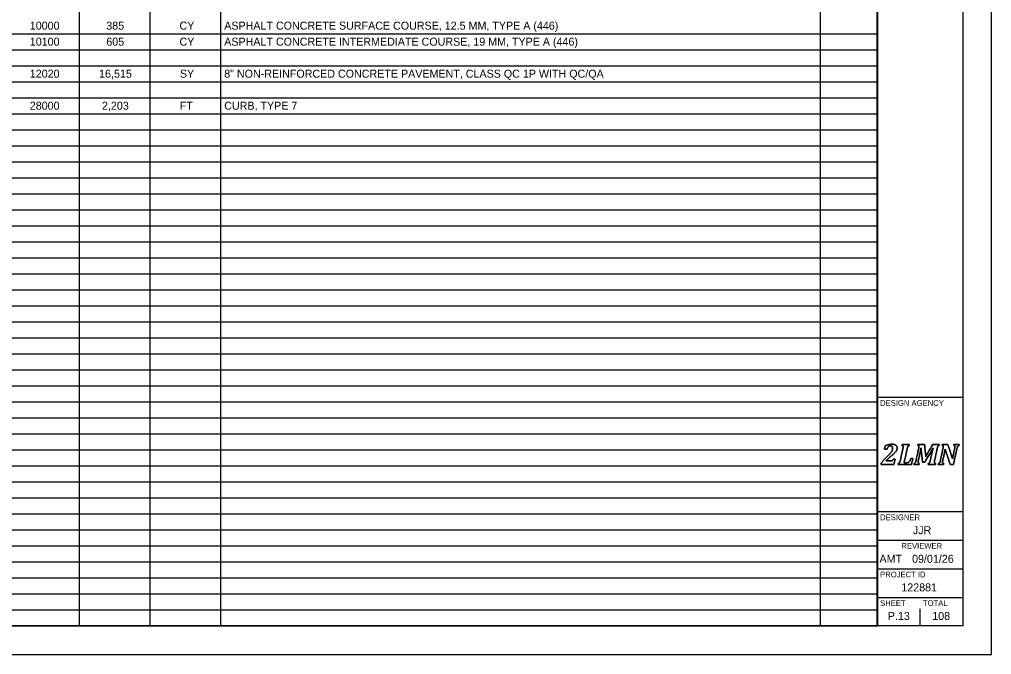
# Model space of a CAD drawing. Extents: x 0 to 34, y 0 to 22.
# Drawn here: x 16.99 to 34, y 0 to 11.11 of the extents above; entities that cross this region are included whole.
import ezdxf

# ---------------------------------------------------------------- set-up
doc = ezdxf.new("R2010")
doc.units = 0
for name, color, linetype in [('SH_Border', 7, 'Continuous'), ('SH_Cut_Line', 7, 'Continuous'), ('SH_Data', 7, 'Continuous'), ('SH_Text', 7, 'Continuous')]:
    doc.layers.add(name, color=color, linetype=linetype)

msp = doc.modelspace()

# ---------------------------------------------------------------- linework, layer by layer
at = {"layer": 'SH_Border'}
for p, q in [((32, 0.5), (32, 21.5)), ((32, 4.5), (33.5, 4.5)), ((32, 2.5), (33.5, 2.5)), ((32, 2), (33.5, 2)), ((32, 1.5), (33.5, 1.5)), ((32, 1), (33.5, 1))]:
    msp.add_line(p, q, dxfattribs=at)
msp.add_lwpolyline([(1.5, 21.5), (33.5, 21.5), (33.5, 0.5), (1.5, 0.5)], close=True, dxfattribs=at)
at = {"layer": 'SH_Cut_Line'}
msp.add_lwpolyline([(0, 0), (34, 0), (34, 22), (0, 22)], close=True, dxfattribs=at)
at = {"layer": 'SH_Data'}
for p, q in [((32.75, 3.5), (32.75, 3.5)), ((32.75, 0.5), (32.75, 0.8)), ((32.375, 0.675), (32.375, 0.675))]:
    msp.add_line(p, q, dxfattribs=at)
for points in [[(32.237, 3.388), (32.246, 3.388), (32.253, 3.389), (32.258, 3.39), (32.263, 3.392), (32.267, 3.394), (32.27, 3.397), (32.273, 3.401), (32.277, 3.408), (32.281, 3.417), (32.281, 3.417), (32.312, 3.417), (32.312, 3.417), (32.312, 3.417), (32.29, 3.326), (32.29, 3.326), (32.29, 3.326), (32.066, 3.326), (32.066, 3.326), (32.066, 3.326), (32.069, 3.343), (32.069, 3.343), (32.078, 3.358), (32.091, 3.375), (32.106, 3.394), (32.122, 3.412), (32.144, 3.435), (32.172, 3.462), (32.197, 3.486), (32.217, 3.506), (32.23, 3.521), (32.243, 3.537), (32.253, 3.551), (32.259, 3.566), (32.266, 3.58), (32.269, 3.595), (32.269, 3.61), (32.269, 3.622), (32.266, 3.632), (32.26, 3.64), (32.253, 3.647), (32.245, 3.65), (32.234, 3.65), (32.22, 3.65), (32.208, 3.646), (32.198, 3.636), (32.188, 3.627), (32.18, 3.613), (32.172, 3.593), (32.172, 3.593), (32.126, 3.593), (32.126, 3.593), (32.126, 3.593), (32.14, 3.654), (32.14, 3.654), (32.166, 3.663), (32.188, 3.669), (32.205, 3.673), (32.223, 3.676), (32.24, 3.678), (32.258, 3.678), (32.278, 3.678), (32.295, 3.675), (32.309, 3.669), (32.322, 3.664), (32.332, 3.656), (32.339, 3.646), (32.345, 3.637), (32.348, 3.626), (32.348, 3.613), (32.348, 3.602), (32.346, 3.591), (32.342, 3.581), (32.339, 3.571), (32.333, 3.56), (32.324, 3.549), (32.315, 3.539), (32.304, 3.526), (32.289, 3.513), (32.275, 3.499), (32.254, 3.482), (32.228, 3.46), (32.216, 3.45), (32.202, 3.438), (32.188, 3.425), (32.174, 3.412), (32.162, 3.4), (32.154, 3.391), (32.154, 3.391), (32.153, 3.388), (32.153, 3.388), (32.153, 3.388), (32.237, 3.388), (32.237, 3.388)], [(32.237, 3.388), (32.237, 3.388), (32.153, 3.388), (32.153, 3.388), (32.153, 3.388), (32.154, 3.391), (32.154, 3.391), (32.162, 3.4), (32.174, 3.412), (32.188, 3.425), (32.202, 3.438), (32.216, 3.45), (32.228, 3.46), (32.254, 3.482), (32.275, 3.499), (32.289, 3.513), (32.304, 3.526), (32.315, 3.539), (32.324, 3.549), (32.333, 3.56), (32.339, 3.571), (32.342, 3.581), (32.346, 3.591), (32.348, 3.602), (32.348, 3.613), (32.348, 3.626), (32.345, 3.637), (32.339, 3.646), (32.332, 3.656), (32.322, 3.664), (32.309, 3.669), (32.295, 3.675), (32.278, 3.678), (32.258, 3.678), (32.24, 3.678), (32.223, 3.676), (32.205, 3.673), (32.188, 3.669), (32.166, 3.663), (32.14, 3.654), (32.14, 3.654), (32.126, 3.593), (32.126, 3.593), (32.126, 3.593), (32.172, 3.593), (32.172, 3.593), (32.18, 3.613), (32.188, 3.627), (32.198, 3.636), (32.208, 3.646), (32.22, 3.65), (32.234, 3.65), (32.245, 3.65), (32.253, 3.647), (32.26, 3.64), (32.266, 3.632), (32.269, 3.622), (32.269, 3.61), (32.269, 3.595), (32.266, 3.58), (32.259, 3.566), (32.253, 3.551), (32.243, 3.537), (32.23, 3.521), (32.217, 3.506), (32.197, 3.486), (32.172, 3.462), (32.144, 3.435), (32.122, 3.412), (32.106, 3.394), (32.091, 3.375), (32.078, 3.358), (32.069, 3.343), (32.069, 3.343), (32.066, 3.326), (32.066, 3.326), (32.066, 3.326), (32.29, 3.326), (32.29, 3.326), (32.29, 3.326), (32.312, 3.417), (32.312, 3.417), (32.312, 3.417), (32.281, 3.417), (32.281, 3.417), (32.277, 3.408), (32.273, 3.401), (32.27, 3.397), (32.267, 3.394), (32.263, 3.392), (32.258, 3.39), (32.253, 3.389), (32.246, 3.388), (32.237, 3.388)], [(32.518, 3.356), (32.527, 3.356), (32.533, 3.357), (32.538, 3.358), (32.542, 3.36), (32.546, 3.362), (32.55, 3.365), (32.554, 3.368), (32.558, 3.372), (32.562, 3.377), (32.567, 3.382), (32.571, 3.388), (32.576, 3.397), (32.58, 3.405), (32.585, 3.415), (32.589, 3.427), (32.589, 3.427), (32.624, 3.427), (32.624, 3.427), (32.624, 3.427), (32.598, 3.326), (32.598, 3.326), (32.598, 3.326), (32.365, 3.326), (32.365, 3.326), (32.365, 3.326), (32.369, 3.343), (32.369, 3.343), (32.376, 3.345), (32.381, 3.348), (32.385, 3.351), (32.389, 3.355), (32.392, 3.36), (32.395, 3.366), (32.398, 3.373), (32.4, 3.382), (32.403, 3.395), (32.403, 3.395), (32.449, 3.605), (32.449, 3.605), (32.452, 3.615), (32.453, 3.625), (32.453, 3.635), (32.453, 3.642), (32.451, 3.647), (32.448, 3.651), (32.444, 3.654), (32.439, 3.656), (32.432, 3.657), (32.432, 3.657), (32.435, 3.674), (32.435, 3.674), (32.435, 3.674), (32.563, 3.674), (32.563, 3.674), (32.563, 3.674), (32.559, 3.657), (32.559, 3.657), (32.552, 3.655), (32.547, 3.652), (32.543, 3.649), (32.539, 3.645), (32.536, 3.64), (32.533, 3.634), (32.531, 3.627), (32.528, 3.618), (32.525, 3.605), (32.525, 3.605), (32.47, 3.356), (32.47, 3.356), (32.47, 3.356), (32.518, 3.356), (32.518, 3.356)], [(32.518, 3.356), (32.518, 3.356), (32.47, 3.356), (32.47, 3.356), (32.47, 3.356), (32.525, 3.605), (32.525, 3.605), (32.528, 3.618), (32.531, 3.627), (32.533, 3.634), (32.536, 3.64), (32.539, 3.645), (32.543, 3.649), (32.547, 3.652), (32.552, 3.655), (32.559, 3.657), (32.559, 3.657), (32.563, 3.674), (32.563, 3.674), (32.563, 3.674), (32.435, 3.674), (32.435, 3.674), (32.435, 3.674), (32.432, 3.657), (32.432, 3.657), (32.439, 3.656), (32.444, 3.654), (32.448, 3.651), (32.451, 3.647), (32.453, 3.642), (32.453, 3.635), (32.453, 3.625), (32.452, 3.615), (32.449, 3.605), (32.449, 3.605), (32.403, 3.395), (32.403, 3.395), (32.4, 3.382), (32.398, 3.373), (32.395, 3.366), (32.392, 3.36), (32.389, 3.355), (32.385, 3.351), (32.381, 3.348), (32.376, 3.345), (32.369, 3.343), (32.369, 3.343), (32.365, 3.326), (32.365, 3.326), (32.365, 3.326), (32.598, 3.326), (32.598, 3.326), (32.598, 3.326), (32.624, 3.427), (32.624, 3.427), (32.624, 3.427), (32.589, 3.427), (32.589, 3.427), (32.585, 3.415), (32.58, 3.405), (32.576, 3.397), (32.571, 3.388), (32.567, 3.382), (32.562, 3.377), (32.558, 3.372), (32.554, 3.368), (32.55, 3.365), (32.546, 3.362), (32.542, 3.36), (32.538, 3.358), (32.533, 3.357), (32.527, 3.356), (32.518, 3.356)], [(32.829, 3.674), (32.829, 3.674), (32.849, 3.461), (32.849, 3.461), (32.849, 3.461), (32.969, 3.674), (32.969, 3.674), (32.969, 3.674), (33.087, 3.674), (33.087, 3.674), (33.087, 3.674), (33.084, 3.657), (33.084, 3.657), (33.077, 3.655), (33.071, 3.652), (33.067, 3.649), (33.064, 3.645), (33.06, 3.64), (33.058, 3.634), (33.055, 3.627), (33.052, 3.618), (33.05, 3.605), (33.05, 3.605), (33.003, 3.395), (33.003, 3.395), (33.002, 3.39), (33.002, 3.387), (33.001, 3.384), (33.001, 3.382), (33.001, 3.379), (33, 3.376), (33, 3.373), (33, 3.369), (33, 3.365), (33, 3.358), (33.002, 3.353), (33.005, 3.349), (33.008, 3.346), (33.014, 3.344), (33.021, 3.343), (33.021, 3.343), (33.018, 3.326), (33.018, 3.326), (33.018, 3.326), (32.89, 3.326), (32.89, 3.326), (32.89, 3.326), (32.893, 3.343), (32.893, 3.343), (32.9, 3.345), (32.906, 3.348), (32.91, 3.351), (32.914, 3.355), (32.917, 3.36), (32.919, 3.366), (32.922, 3.373), (32.925, 3.382), (32.928, 3.395), (32.928, 3.395), (32.951, 3.502), (32.951, 3.502), (32.954, 3.513), (32.957, 3.529), (32.962, 3.548), (32.967, 3.568), (32.972, 3.588), (32.978, 3.609), (32.978, 3.609), (32.973, 3.609), (32.973, 3.609), (32.965, 3.594), (32.957, 3.579), (32.948, 3.563), (32.948, 3.563), (32.833, 3.364), (32.833, 3.364), (32.833, 3.364), (32.792, 3.364), (32.792, 3.364), (32.792, 3.364), (32.775, 3.518), (32.775, 3.518), (32.773, 3.537), (32.772, 3.554), (32.77, 3.569), (32.769, 3.583), (32.768, 3.597), (32.768, 3.611), (32.768, 3.611), (32.764, 3.611), (32.764, 3.611), (32.761, 3.596), (32.758, 3.578), (32.755, 3.558), (32.751, 3.538), (32.747, 3.521), (32.744, 3.507), (32.744, 3.507), (32.72, 3.395), (32.72, 3.395), (32.719, 3.39), (32.718, 3.387), (32.718, 3.384), (32.717, 3.382), (32.717, 3.379), (32.717, 3.376), (32.717, 3.373), (32.716, 3.369), (32.716, 3.365), (32.716, 3.358), (32.718, 3.353), (32.721, 3.349), (32.725, 3.346), (32.73, 3.344), (32.738, 3.343), (32.738, 3.343), (32.734, 3.326), (32.734, 3.326), (32.734, 3.326), (32.641, 3.326), (32.641, 3.326), (32.641, 3.326), (32.644, 3.343), (32.644, 3.343), (32.651, 3.345), (32.657, 3.348), (32.661, 3.351), (32.665, 3.355), (32.668, 3.36), (32.67, 3.366), (32.673, 3.373), (32.676, 3.382), (32.679, 3.395), (32.679, 3.395), (32.725, 3.605), (32.725, 3.605), (32.727, 3.615), (32.728, 3.625), (32.728, 3.635), (32.728, 3.642), (32.727, 3.647), (32.723, 3.651), (32.72, 3.654), (32.715, 3.656), (32.707, 3.657), (32.707, 3.657), (32.711, 3.674), (32.711, 3.674), (32.711, 3.674), (32.829, 3.674), (32.829, 3.674)], [(32.829, 3.674), (32.829, 3.674), (32.711, 3.674), (32.711, 3.674), (32.711, 3.674), (32.707, 3.657), (32.707, 3.657), (32.715, 3.656), (32.72, 3.654), (32.723, 3.651), (32.727, 3.647), (32.728, 3.642), (32.728, 3.635), (32.728, 3.625), (32.727, 3.615), (32.725, 3.605), (32.725, 3.605), (32.679, 3.395), (32.679, 3.395), (32.676, 3.382), (32.673, 3.373), (32.67, 3.366), (32.668, 3.36), (32.665, 3.355), (32.661, 3.351), (32.657, 3.348), (32.651, 3.345), (32.644, 3.343), (32.644, 3.343), (32.641, 3.326), (32.641, 3.326), (32.641, 3.326), (32.734, 3.326), (32.734, 3.326), (32.734, 3.326), (32.738, 3.343), (32.738, 3.343), (32.73, 3.344), (32.725, 3.346), (32.721, 3.349), (32.718, 3.353), (32.716, 3.358), (32.716, 3.365), (32.716, 3.369), (32.717, 3.373), (32.717, 3.376), (32.717, 3.379), (32.717, 3.382), (32.718, 3.384), (32.718, 3.387), (32.719, 3.39), (32.72, 3.395), (32.72, 3.395), (32.744, 3.507), (32.744, 3.507), (32.747, 3.521), (32.751, 3.538), (32.755, 3.558), (32.758, 3.578), (32.761, 3.596), (32.764, 3.611), (32.764, 3.611), (32.768, 3.611), (32.768, 3.611), (32.768, 3.597), (32.769, 3.583), (32.77, 3.569), (32.772, 3.554), (32.773, 3.537), (32.775, 3.518), (32.775, 3.518), (32.792, 3.364), (32.792, 3.364), (32.792, 3.364), (32.833, 3.364), (32.833, 3.364), (32.833, 3.364), (32.948, 3.563), (32.948, 3.563), (32.957, 3.579), (32.965, 3.594), (32.973, 3.609), (32.973, 3.609), (32.978, 3.609), (32.978, 3.609), (32.972, 3.588), (32.967, 3.568), (32.962, 3.548), (32.957, 3.529), (32.954, 3.513), (32.951, 3.502), (32.951, 3.502), (32.928, 3.395), (32.928, 3.395), (32.925, 3.382), (32.922, 3.373), (32.919, 3.366), (32.917, 3.36), (32.914, 3.355), (32.91, 3.351), (32.906, 3.348), (32.9, 3.345), (32.893, 3.343), (32.893, 3.343), (32.89, 3.326), (32.89, 3.326), (32.89, 3.326), (33.018, 3.326), (33.018, 3.326), (33.018, 3.326), (33.021, 3.343), (33.021, 3.343), (33.014, 3.344), (33.008, 3.346), (33.005, 3.349), (33.002, 3.353), (33, 3.358), (33, 3.365), (33, 3.369), (33, 3.373), (33, 3.376), (33.001, 3.379), (33.001, 3.382), (33.001, 3.384), (33.002, 3.387), (33.002, 3.39), (33.003, 3.395), (33.003, 3.395), (33.05, 3.605), (33.05, 3.605), (33.052, 3.618), (33.055, 3.627), (33.058, 3.634), (33.06, 3.64), (33.064, 3.645), (33.067, 3.649), (33.071, 3.652), (33.077, 3.655), (33.084, 3.657), (33.084, 3.657), (33.087, 3.674), (33.087, 3.674), (33.087, 3.674), (32.969, 3.674), (32.969, 3.674), (32.969, 3.674), (32.849, 3.461), (32.849, 3.461), (32.849, 3.461), (32.829, 3.674), (32.829, 3.674)], [(33.137, 3.674), (33.137, 3.674), (33.234, 3.674), (33.234, 3.674), (33.234, 3.674), (33.283, 3.53), (33.283, 3.53), (33.296, 3.49), (33.307, 3.456), (33.315, 3.426), (33.315, 3.426), (33.318, 3.426), (33.318, 3.426), (33.323, 3.455), (33.329, 3.488), (33.337, 3.523), (33.337, 3.523), (33.355, 3.605), (33.355, 3.605), (33.357, 3.615), (33.358, 3.625), (33.358, 3.635), (33.358, 3.642), (33.357, 3.647), (33.353, 3.651), (33.35, 3.654), (33.345, 3.656), (33.337, 3.657), (33.337, 3.657), (33.341, 3.674), (33.341, 3.674), (33.341, 3.674), (33.434, 3.674), (33.434, 3.674), (33.434, 3.674), (33.431, 3.657), (33.431, 3.657), (33.424, 3.655), (33.418, 3.652), (33.414, 3.649), (33.41, 3.645), (33.407, 3.64), (33.405, 3.634), (33.402, 3.627), (33.399, 3.618), (33.396, 3.605), (33.396, 3.605), (33.335, 3.326), (33.335, 3.326), (33.335, 3.326), (33.277, 3.326), (33.277, 3.326), (33.277, 3.326), (33.216, 3.504), (33.216, 3.504), (33.211, 3.518), (33.207, 3.531), (33.204, 3.543), (33.2, 3.556), (33.195, 3.571), (33.19, 3.59), (33.19, 3.59), (33.186, 3.59), (33.186, 3.59), (33.185, 3.579), (33.182, 3.563), (33.179, 3.543), (33.175, 3.523), (33.17, 3.501), (33.165, 3.478), (33.165, 3.478), (33.147, 3.395), (33.147, 3.395), (33.146, 3.39), (33.145, 3.387), (33.145, 3.384), (33.144, 3.382), (33.144, 3.379), (33.144, 3.376), (33.143, 3.373), (33.143, 3.369), (33.143, 3.365), (33.143, 3.358), (33.145, 3.353), (33.148, 3.349), (33.152, 3.346), (33.157, 3.344), (33.164, 3.343), (33.164, 3.343), (33.161, 3.326), (33.161, 3.326), (33.161, 3.326), (33.067, 3.326), (33.067, 3.326), (33.067, 3.326), (33.071, 3.343), (33.071, 3.343), (33.078, 3.345), (33.083, 3.348), (33.087, 3.351), (33.091, 3.355), (33.094, 3.36), (33.097, 3.366), (33.1, 3.373), (33.102, 3.382), (33.105, 3.395), (33.105, 3.395), (33.151, 3.605), (33.151, 3.605), (33.154, 3.615), (33.155, 3.625), (33.155, 3.635), (33.155, 3.642), (33.153, 3.647), (33.15, 3.651), (33.146, 3.654), (33.141, 3.656), (33.134, 3.657), (33.134, 3.657), (33.137, 3.674), (33.137, 3.674)], [(33.137, 3.674), (33.137, 3.674), (33.134, 3.657), (33.134, 3.657), (33.141, 3.656), (33.146, 3.654), (33.15, 3.651), (33.153, 3.647), (33.155, 3.642), (33.155, 3.635), (33.155, 3.625), (33.154, 3.615), (33.151, 3.605), (33.151, 3.605), (33.105, 3.395), (33.105, 3.395), (33.102, 3.382), (33.1, 3.373), (33.097, 3.366), (33.094, 3.36), (33.091, 3.355), (33.087, 3.351), (33.083, 3.348), (33.078, 3.345), (33.071, 3.343), (33.071, 3.343), (33.067, 3.326), (33.067, 3.326), (33.067, 3.326), (33.161, 3.326), (33.161, 3.326), (33.161, 3.326), (33.164, 3.343), (33.164, 3.343), (33.157, 3.344), (33.152, 3.346), (33.148, 3.349), (33.145, 3.353), (33.143, 3.358), (33.143, 3.365), (33.143, 3.369), (33.143, 3.373), (33.144, 3.376), (33.144, 3.379), (33.144, 3.382), (33.145, 3.384), (33.145, 3.387), (33.146, 3.39), (33.147, 3.395), (33.147, 3.395), (33.165, 3.478), (33.165, 3.478), (33.17, 3.501), (33.175, 3.523), (33.179, 3.543), (33.182, 3.563), (33.185, 3.579), (33.186, 3.59), (33.186, 3.59), (33.19, 3.59), (33.19, 3.59), (33.195, 3.571), (33.2, 3.556), (33.204, 3.543), (33.207, 3.531), (33.211, 3.518), (33.216, 3.504), (33.216, 3.504), (33.277, 3.326), (33.277, 3.326), (33.277, 3.326), (33.335, 3.326), (33.335, 3.326), (33.335, 3.326), (33.396, 3.605), (33.396, 3.605), (33.399, 3.618), (33.402, 3.627), (33.405, 3.634), (33.407, 3.64), (33.41, 3.645), (33.414, 3.649), (33.418, 3.652), (33.424, 3.655), (33.431, 3.657), (33.431, 3.657), (33.434, 3.674), (33.434, 3.674), (33.434, 3.674), (33.341, 3.674), (33.341, 3.674), (33.341, 3.674), (33.337, 3.657), (33.337, 3.657), (33.345, 3.656), (33.35, 3.654), (33.353, 3.651), (33.357, 3.647), (33.358, 3.642), (33.358, 3.635), (33.358, 3.625), (33.357, 3.615), (33.355, 3.605), (33.355, 3.605), (33.337, 3.523), (33.337, 3.523), (33.329, 3.488), (33.323, 3.455), (33.318, 3.426), (33.318, 3.426), (33.315, 3.426), (33.315, 3.426), (33.307, 3.456), (33.296, 3.49), (33.283, 3.53), (33.283, 3.53), (33.234, 3.674), (33.234, 3.674), (33.234, 3.674), (33.137, 3.674), (33.137, 3.674)]]:
    msp.add_open_spline(points, degree=3, dxfattribs=at)
at = {"layer": 'SH_Text'}
for p, q in [((18.036, 21.5), (18.036, 0.5)), ((19.272, 21.5), (19.272, 0.5)), ((20.507, 21.5), (20.507, 0.5)), ((30.999, 21.5), (30.999, 0.5)), ((32.004, 21.5), (32.004, 0.5)), ((1.5, 10.86), (32.004, 10.86)), ((1.5, 10.58), (32.004, 10.58)), ((1.5, 10.3), (32.004, 10.3)), ((1.5, 10.02), (32.004, 10.02)), ((1.5, 9.74), (32.004, 9.74)), ((1.5, 9.46), (32.004, 9.46)), ((1.5, 9.18), (32.004, 9.18)), ((1.5, 8.9), (32.004, 8.9)), ((1.5, 8.62), (32.004, 8.62)), ((1.5, 8.34), (32.004, 8.34)), ((1.5, 8.06), (32.004, 8.06)), ((1.5, 7.78), (32.004, 7.78)), ((1.5, 7.5), (32.004, 7.5)), ((1.5, 7.22), (32.004, 7.22)), ((1.5, 6.94), (32.004, 6.94)), ((1.5, 6.66), (32.004, 6.66)), ((1.5, 6.38), (32.004, 6.38)), ((1.5, 6.1), (32.004, 6.1)), ((1.5, 5.82), (32.004, 5.82)), ((1.5, 5.54), (32.004, 5.54)), ((1.5, 5.26), (32.004, 5.26)), ((1.5, 4.98), (32.004, 4.98)), ((1.5, 4.7), (32.004, 4.7)), ((1.5, 4.42), (32.004, 4.42)), ((1.5, 4.14), (32.004, 4.14)), ((1.5, 3.86), (32.004, 3.86)), ((1.5, 3.58), (32.004, 3.58)), ((1.5, 3.3), (32.004, 3.3)), ((1.5, 3.02), (32.004, 3.02)), ((1.5, 2.74), (32.004, 2.74)), ((1.5, 2.46), (32.004, 2.46)), ((1.5, 2.18), (32.004, 2.18)), ((1.5, 1.9), (32.004, 1.9)), ((1.5, 1.62), (32.004, 1.62)), ((1.5, 1.34), (32.004, 1.34)), ((1.5, 1.06), (32.004, 1.06)), ((1.5, 0.78), (32.004, 0.78)), ((1.5, 0.5), (32.004, 0.5))]:
    msp.add_line(p, q, dxfattribs=at)

# ---------------------------------------------------------------- texts
at = {"layer": 'SH_Data'}
for s, height, p in [('DESIGN AGENCY', 0.1, (32.05, 4.35)), ('DESIGNER', 0.1, (32.05, 2.35)), ('JJR', 0.14, (32.624, 2.105)), ('REVIEWER', 0.1, (32.422, 1.85)), ('AMT', 0.14, (32.039, 1.605)), ('09/01/26', 0.14, (32.609, 1.605)), ('PROJECT ID', 0.1, (32.05, 1.35)), ('122881', 0.14, (32.421, 1.105)), ('SHEET', 0.1, (32.05, 0.85)), ('TOTAL', 0.1, (32.8, 0.85)), ('P.13', 0.14, (32.185, 0.605)), ('108', 0.14, (32.962, 0.605))]:
    msp.add_text(s, height=height, dxfattribs=at).set_placement(p)
at = {"layer": 'SH_Text'}
for s, p in [('10000', (17.171, 10.93)), ('385', (18.509, 10.93)), ('CY', (19.79, 10.93)), ('ASPHALT CONCRETE SURFACE COURSE, 12.5 MM, TYPE A (446)', (20.573, 10.93)), ('10100', (17.171, 10.65)), ('605', (18.509, 10.65)), ('CY', (19.79, 10.65)), ('ASPHALT CONCRETE INTERMEDIATE COURSE, 19 MM, TYPE A (446)', (20.573, 10.65)), ('12020', (17.171, 10.09)), ('16,515', (18.384, 10.09)), ('SY', (19.798, 10.09)), ('8" NON-REINFORCED CONCRETE PAVEMENT, CLASS QC 1P WITH QC/QA', (20.573, 10.09)), ('28000', (17.171, 9.53)), ('2,203', (18.434, 9.53)), ('FT', (19.796, 9.53)), ('CURB, TYPE 7', (20.573, 9.53))]:
    msp.add_text(s, height=0.14, dxfattribs=at).set_placement(p)

doc.saveas('drawing.dxf')
